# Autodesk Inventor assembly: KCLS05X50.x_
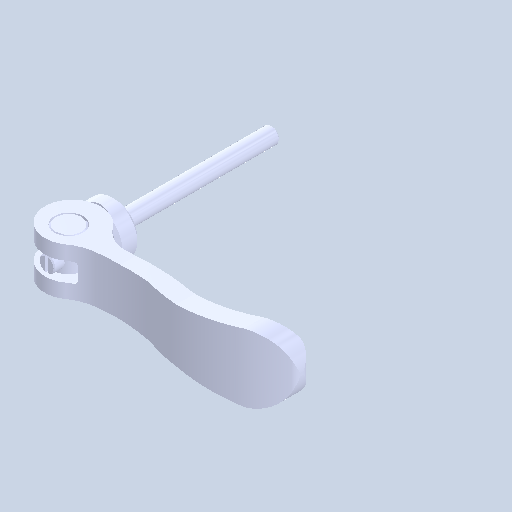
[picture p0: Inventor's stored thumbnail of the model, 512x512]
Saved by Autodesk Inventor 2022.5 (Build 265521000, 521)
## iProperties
Created: 2024-08
Part Number: KCLS05X50.x_
Document SubType Name: Assembly
Designer: ImaoCorp
Author: ImaoCorp
Sending System: SOLIDWORKS 2022-2022290
MC: AMD64
MC_MODEL: Intel64 Family 6 Model 60 Stepping 3, GenuineIntel
OS: Windows_NT
FRU: Parasolid Version 33.1, build 260,  4-25-2022
FORMAT: text
GUISE: transmit
KEY: FILEKCLS05X50.x_t
DATE: Thu Aug 29 10:54:46 2024
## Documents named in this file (5)
- Y:\5.更新分\2024年対応\1001_KCL\データ\kcls05x50\KCLS05X50.x_.iam
- Y:\5.更新分\2024年対応\1001_KCL\データ\kcls05x50\KCLS05X50_01.ipt
- Y:\5.更新分\2024年対応\1001_KCL\データ\kcls05x50\KCLS05X50_02.ipt
- Y:\5.更新分\2024年対応\1001_KCL\データ\kcls05x50\KCLS05X50_03.ipt
- Y:\5.更新分\2024年対応\1001_KCL\データ\kcls05x50\KCLS05X50_04.ipt
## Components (4 placed, 4 different names)
1. KCLS05X50_01
2. KCLS05X50_02
3. KCLS05X50_03
4. KCLS05X50_04
